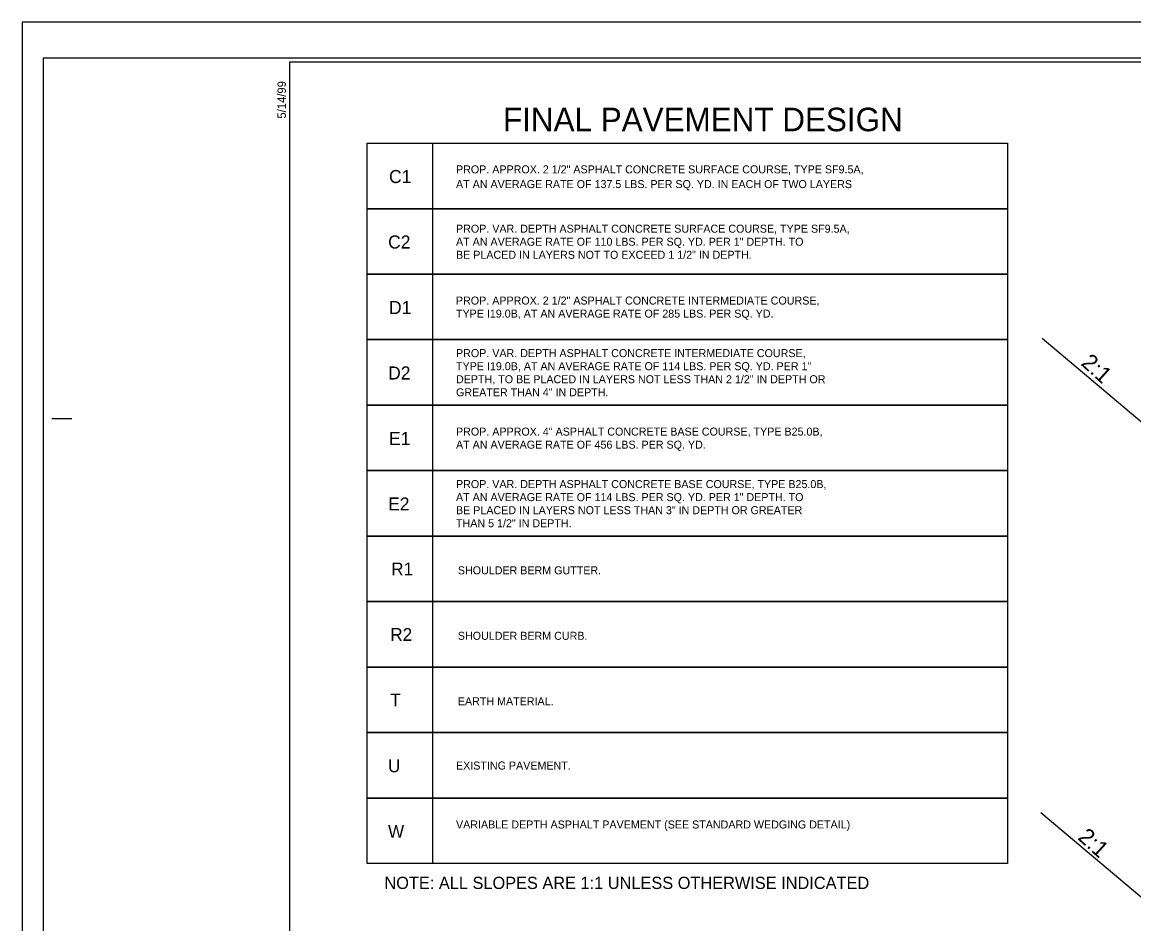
# Model space of a CAD drawing. Extents: x 573693 to 575619, y -55388 to -54288.
# Drawn here: x 573693 to 574388, y -54852 to -54288 of the extents above; entities that cross this region are included whole.
import ezdxf

# ---------------------------------------------------------------- set-up
doc = ezdxf.new("R2010")
doc.units = 0
for name, color, linetype in [('Prop Dimension', 7, 'Continuous'), ('Prop Pavement Schedule Description CELL', 7, 'Continuous'), ('Sheet Border Standard 30in CELL', 7, 'Continuous'), ('Sheet Cutting Line CELL', 7, 'Continuous'), ('Sheet Plot Border Inside CELL', 7, 'Continuous'), ('Sheet Plot Border Outside CELL', 7, 'Continuous'), ('Typical Text Grade Point CELL', 7, 'Continuous')]:
    doc.layers.add(name, color=color, linetype=linetype)

msp = doc.modelspace()

# ---------------------------------------------------------------- linework, layer by layer
at = {"layer": 'Prop Dimension'}
for p, q in [((574403.92, -54548.04), (574330.25, -54485.93)), ((574403.1, -54844.45), (574329.43, -54782.34))]:
    msp.add_line(p, q, dxfattribs=at)
at = {"layer": 'Prop Pavement Schedule Description CELL'}
for points in [[(573949.44, -54404.87), (573908.53, -54404.87), (573908.53, -54363.95), (574308.53, -54363.95), (574308.53, -54404.87), (573949.44, -54404.87), (573949.44, -54363.95)], [(573949.44, -54445.77), (573908.53, -54445.77), (573908.53, -54404.87), (574308.53, -54404.87), (574308.53, -54445.77), (573949.44, -54445.77), (573949.44, -54404.87)], [(573949.44, -54486.68), (573908.53, -54486.68), (573908.53, -54445.77), (574308.53, -54445.77), (574308.53, -54486.68), (573949.44, -54486.68), (573949.44, -54445.77)], [(573949.44, -54527.59), (573908.53, -54527.59), (573908.53, -54486.68), (574308.54, -54486.68), (574308.54, -54527.59), (573949.44, -54527.59), (573949.44, -54486.68)], [(573949.44, -54568.5), (573908.53, -54568.5), (573908.53, -54527.59), (574308.53, -54527.59), (574308.53, -54568.5), (573949.44, -54568.5), (573949.44, -54527.59)], [(573949.44, -54609.41), (573908.53, -54609.41), (573908.53, -54568.5), (574308.53, -54568.5), (574308.53, -54609.41), (573949.44, -54609.41), (573949.44, -54568.5)], [(573949.44, -54650.32), (573908.53, -54650.32), (573908.53, -54609.41), (574308.53, -54609.41), (574308.53, -54650.32), (573949.44, -54650.32), (573949.44, -54609.41)], [(573949.44, -54691.22), (573908.53, -54691.22), (573908.53, -54650.32), (574308.53, -54650.32), (574308.53, -54691.22), (573949.44, -54691.22), (573949.44, -54650.32)], [(573949.44, -54732.13), (573908.53, -54732.13), (573908.53, -54691.22), (574308.53, -54691.22), (574308.53, -54732.13), (573949.44, -54732.13), (573949.44, -54691.22)], [(573949.44, -54773.04), (573908.53, -54773.04), (573908.53, -54732.13), (574308.53, -54732.13), (574308.53, -54773.04), (573949.44, -54773.04), (573949.44, -54732.13)], [(573949.44, -54813.95), (573908.53, -54813.95), (573908.53, -54773.04), (574308.54, -54773.04), (574308.54, -54813.95), (573949.44, -54813.95), (573949.44, -54773.04)]]:
    msp.add_lwpolyline(points, dxfattribs=at)
at = {"layer": 'Sheet Border Standard 30in CELL'}
for p, q in [((573860.97, -54313.39), (573860.97, -54313.39)), ((573711.47, -54535.89), (573723.97, -54535.89))]:
    msp.add_line(p, q, dxfattribs=at)
msp.add_lwpolyline([(575359.97, -54313.39), (573859.97, -54313.39), (573859.97, -55363.39), (575359.97, -55363.39)], close=True, dxfattribs=at)
at = {"layer": 'Sheet Cutting Line CELL'}
for p, q in [((575376.97, -54288.39), (573692.97, -54288.39)), ((573692.97, -54288.39), (573692.97, -55388.39))]:
    msp.add_line(p, q, dxfattribs=at)
at = {"layer": 'Sheet Plot Border Inside CELL'}
msp.add_lwpolyline([(575372.47, -54310.84), (573705.97, -54310.84), (573705.97, -55365.94), (575372.47, -55365.94)], close=True, dxfattribs=at)
at = {"layer": 'Sheet Plot Border Outside CELL'}
msp.add_lwpolyline([(575376.97, -54288.39), (573692.97, -54288.39), (573692.97, -55388.39), (575376.97, -55388.39)], close=True, dxfattribs=at)

# ---------------------------------------------------------------- texts
at = {"layer": 'Prop Pavement Schedule Description CELL'}
for s, height, p in [('C1', 8.167, (573922.17, -54388.87)), ('PROP. APPROX. 2 1/2" ASPHALT CONCRETE SURFACE COURSE, TYPE SF9.5A,', 5, (573964.02, -54382.81)), ('AT AN AVERAGE RATE OF 137.5 LBS. PER SQ. YD. IN EACH OF TWO LAYERS', 5, (573964.02, -54392.01)), ('PROP. VAR. DEPTH ASPHALT CONCRETE SURFACE COURSE, TYPE SF9.5A,', 5, (573964.02, -54419.87)), ('C2', 8.167, (573921.6, -54429.77)), ('AT AN AVERAGE RATE OF 110 LBS. PER SQ. YD. PER 1" DEPTH. TO', 5, (573964.02, -54428.02)), ('BE PLACED IN LAYERS NOT TO EXCEED 1 1/2" IN DEPTH.', 5, (573964.02, -54436.18)), ('PROP. APPROX. 2 1/2" ASPHALT CONCRETE INTERMEDIATE COURSE,', 5, (573963.98, -54464.77)), ('D1', 8.167, (573922.17, -54470.68)), ('TYPE I19.0B, AT AN AVERAGE RATE OF 285 LBS. PER SQ. YD.', 5, (573963.98, -54472.93)), ('PROP. VAR. DEPTH ASPHALT CONCRETE INTERMEDIATE COURSE,', 5, (573964.02, -54497.6)), ('TYPE I19.0B, AT AN AVERAGE RATE OF 114 LBS. PER SQ. YD. PER 1" ', 5, (573964.02, -54505.76)), ('D2', 8.167, (573921.6, -54511.59)), ('DEPTH, TO BE PLACED IN LAYERS NOT LESS THAN 2 1/2" IN DEPTH OR', 5, (573964.02, -54513.92)), ('GREATER THAN 4" IN DEPTH.', 5, (573964.02, -54522.07)), ('PROP. APPROX. 4" ASPHALT CONCRETE BASE COURSE, TYPE B25.0B,', 5, (573964.02, -54546.63)), ('E1', 8.167, (573922.17, -54552.51)), ('AT AN AVERAGE RATE OF 456 LBS. PER SQ. YD.', 5, (573964.02, -54554.79)), ('PROP. VAR. DEPTH ASPHALT CONCRETE BASE COURSE, TYPE B25.0B,', 5, (573964.02, -54579.42)), ('E2', 8.167, (573921.6, -54593.42)), ('AT AN AVERAGE RATE OF 114 LBS. PER SQ. YD. PER 1" DEPTH. TO', 5, (573964.02, -54587.57)), ('BE PLACED IN LAYERS NOT LESS THAN 3" IN DEPTH OR GREATER', 5, (573964.02, -54595.73)), ('THAN 5 1/2" IN DEPTH.', 5, (573964.02, -54603.89)), ('R1', 8, (573923.51, -54633.94)), ('SHOULDER BERM GUTTER.', 5, (573965.17, -54633.29)), ('R2', 8, (573922.93, -54674.85)), ('SHOULDER BERM CURB.', 5, (573965.17, -54674.2)), ('T ', 8, (573922.87, -54715.76)), ('EARTH MATERIAL.', 5, (573965.17, -54715.11)), ('U ', 8, (573921.54, -54756.96)), ('EXISTING PAVEMENT.', 5, (573964.02, -54755.26)), ('W ', 8, (573921.54, -54797.87)), ('VARIABLE DEPTH ASPHALT PAVEMENT (SEE STANDARD WEDGING DETAIL)', 5, (573964.02, -54792.08))]:
    msp.add_text(s, height=height, dxfattribs=at).set_placement(p)
at = {"layer": 'Sheet Border Standard 30in CELL'}
msp.add_text('5/14/99', height=5.25, rotation=90, dxfattribs=at).set_placement((573857.72, -54348.59))
at = {"layer": 'Typical Text Grade Point CELL'}
for s, height, p in [('FINAL PAVEMENT DESIGN', 14.6807, (573993.37, -54356.48)), ('NOTE: ALL SLOPES ARE 1:1 UNLESS OTHERWISE INDICATED', 7.634, (573919.29, -54829.88))]:
    msp.add_text(s, height=height, dxfattribs=at).set_placement(p)
for p in [(574354, -54502.09), (574351.98, -54798.39)]:
    msp.add_text('2:1', height=10.179, rotation=317.84204, dxfattribs=at).set_placement(p)

doc.saveas('drawing.dxf')
